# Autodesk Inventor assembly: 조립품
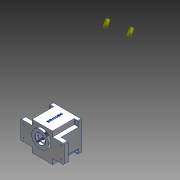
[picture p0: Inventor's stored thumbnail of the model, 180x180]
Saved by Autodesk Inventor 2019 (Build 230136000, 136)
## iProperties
Created: 2020-01
Part Number: 조립품
Material: 일반
Document SubType Name: Assembly
Designer: 323-8
Author: 323-8
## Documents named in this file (5)
- C:\Users\323-8\Desktop\700119V1001\조립품.iam
- C:\Users\323-8\Desktop\700119V1001\본체.ipt
- C:\Users\323-8\Desktop\700119V1001\커버.ipt
- C:\Users\323-8\Desktop\700119V1001\메인 축.ipt
- C:\Users\323-8\Desktop\700119V1001\베어링 608.ipt
